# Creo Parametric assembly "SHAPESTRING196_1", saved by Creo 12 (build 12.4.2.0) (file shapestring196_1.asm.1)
Units: Custom; MM, KILOGRAM, SECS

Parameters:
  PTC_WM_ITERATION = "0"
  PTC_WM_VERSION = "-.0"
  PTC_WM_LIFECYCLE_STATE = "In Work"
  PTC_WM_LIFECYCLE = "MO_CADDocument"
  PTC_WM_CREATED_BY = "Maximilian Roepper (Z0017RMS: MO)"
  PTC_WM_CREATED_ON = "18-Sep-26 11:36:42 AM"
  PTC_WM_MODIFIED_BY = "Maximilian Roepper (Z0017RMS: MO)"
  PTC_WM_MODIFIED_ON = "18-Sep-26 11:36:46 AM"
  PDMLINKNUMBER = "PDM000071455088"
  PTC_WM_NUMBER = "PDM000071455088"

Other parameters: WEIGHT, WEIGHT_FACTOR, WEIGHT_ADD, MC_ERRORS, SUPPLIER

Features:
  1. coordinate system
  2. imported feature
  3. component "SHAPESTRING085_1"
  4. component "SHAPESTRING192_1"
  5. component "SHAPESTRING193_1"
  6. component "SHAPESTRING194_1"
  7. component "SHAPESTRING195_1"

Other named items: DRW_VIEW_ORG, ROUGH-GROB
